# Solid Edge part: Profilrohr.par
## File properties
Username: bmolnar
Dokumentum tartalom típus: 0
Author: bmolnar
Last saved by: bmolnar
Revision: 81
Sűrűség: 0,000 kg/m^3
Pontosság: 0,990
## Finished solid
Body 1: solid body, 63 faces, 178 edges, 112 vertices.
  Faces by surface: cylinder 33, plane 30
  Edges by curve: line 112, circle 66
Bounding box of the edges (mm): 36.000 x 38.400 x 36.000, from (-18, -29.15, -18) to (18, 9.25, 18).
Cylindrical faces by radius (mm): R0.2 x12, R0.5 x12, R3.775 x4, R4.5 x4, R10 x1
Planar faces by outward normal: +x 7, +y 1, +z 7, -x 7, -y 1, -z 7
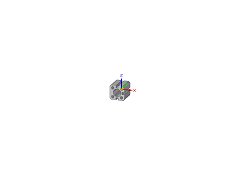
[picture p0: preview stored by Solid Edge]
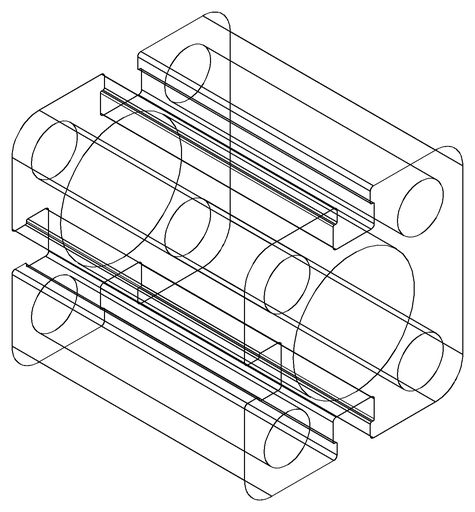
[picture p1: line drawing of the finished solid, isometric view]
